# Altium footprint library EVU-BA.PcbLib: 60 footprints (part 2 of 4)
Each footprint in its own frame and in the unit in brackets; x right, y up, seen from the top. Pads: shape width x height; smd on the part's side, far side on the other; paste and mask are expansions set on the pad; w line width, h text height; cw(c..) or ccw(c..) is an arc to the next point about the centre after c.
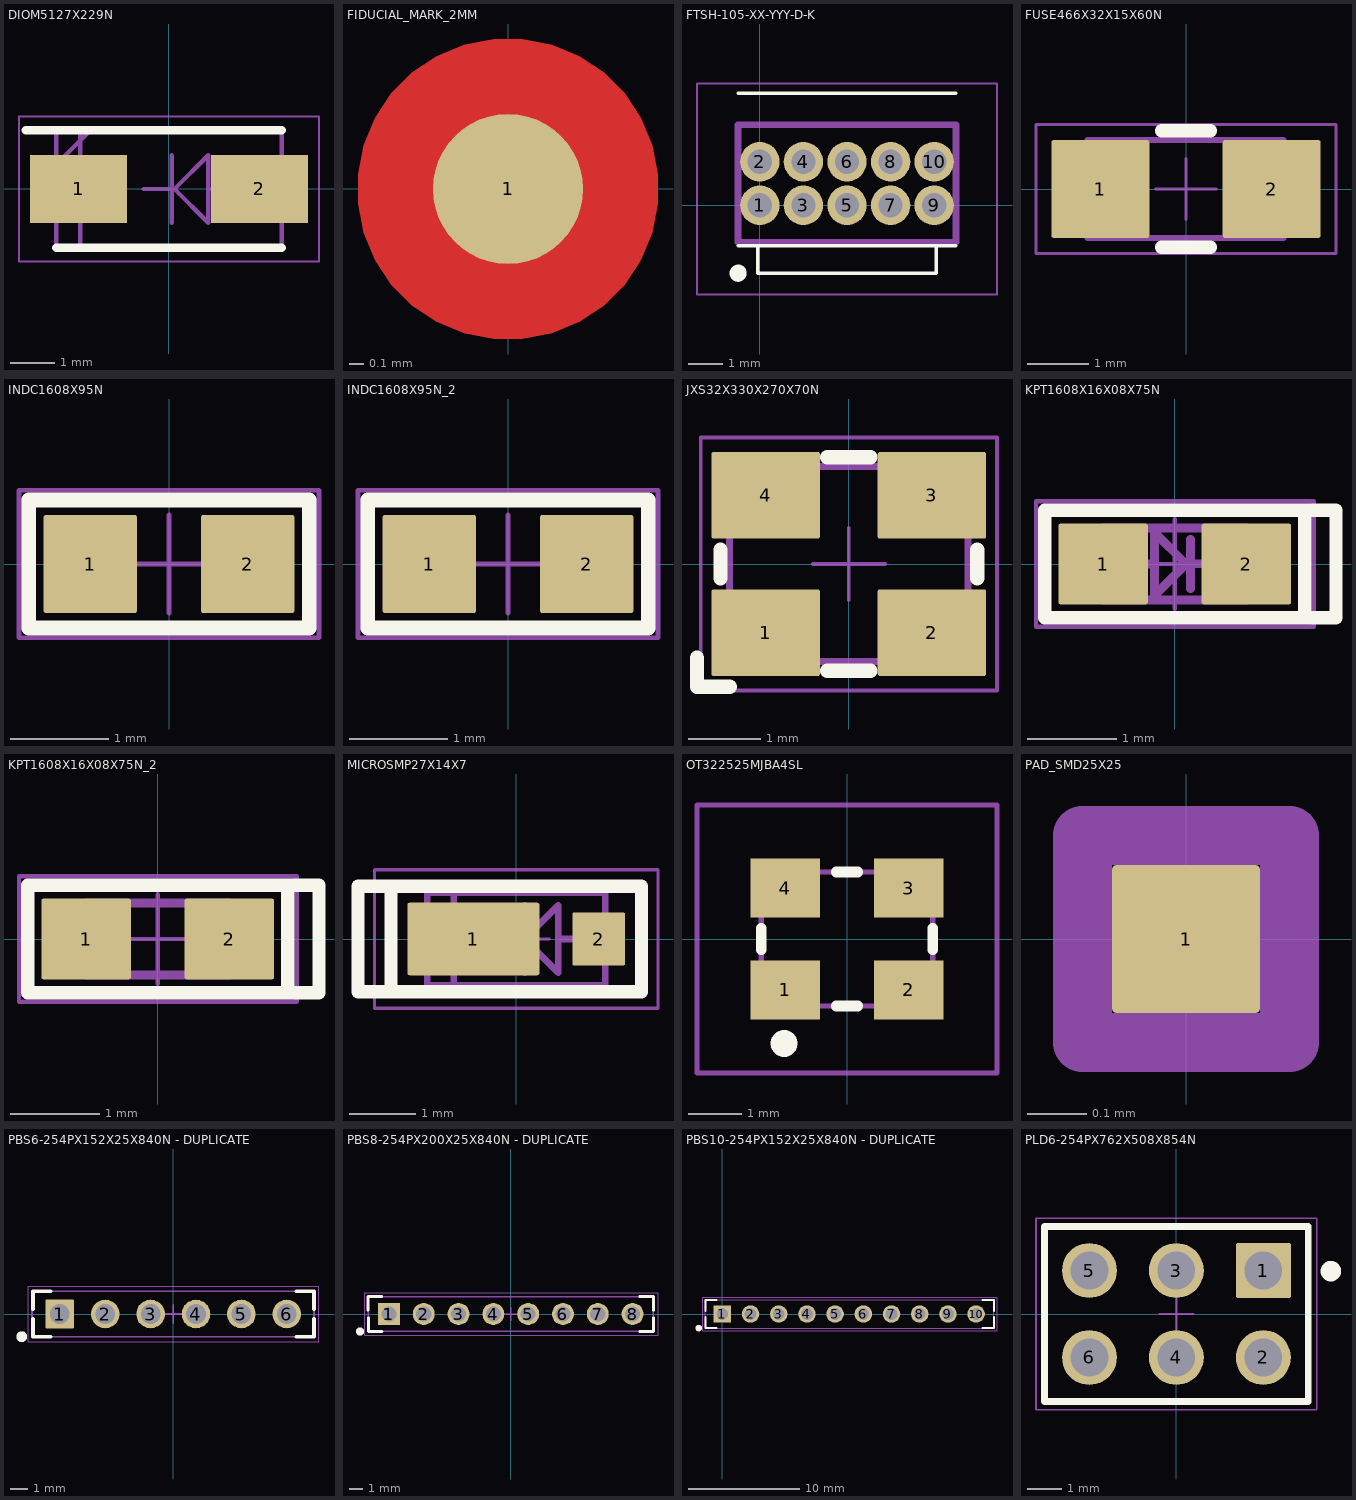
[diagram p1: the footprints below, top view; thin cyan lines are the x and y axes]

## DIOM5127X229N [mm]
pads (2):
  rect 2.2x1.55 smd: 1(-2.05,0) 2(2.05,0)
Top Overlay:
  lines w0.2: -3.24,1.332 -2.825,1.332 2.552,1.332 ; -2.552,-1.332 2.552,-1.332
Top Assembly:
  lines w0.1: -2.014,-1.332 -2.014,1.332 ; -0.572,0 0.064,0 ; 0.064,-0.762 0.064,0.762 ; 0.889,0 1.524,0 ; -2.552,-1.332 2.552,-1.332 2.552,1.332 -2.552,1.332 -2.552,-1.332 ; 0.127,0 0.889,-0.762 0.889,0.762 0.127,0
Mechanical 13:
  lines w0.1: -2.552,0.558 -1.778,1.332 ; -2.552,-1.332 2.552,-1.332 2.552,1.332 -2.552,1.332 -2.552,-1.332
Top Courtyard:
  lines w0.05: -3.4,-1.645 3.4,-1.645 3.4,1.645 -3.4,1.645 -3.4,-1.645
3D body "ES1B-E3_61T.stp": height 2.29, standoff 0, extent -2.552,-1.332 2.552,1.332

## FIDUCIAL_MARK_2MM [mil]
pads (1):
  round 40 smd paste+8.28 mask+20: 1(0,0)
Top Layer:
  pour cut-out: 0,-40 -3.94,-40 -11.67,-38.46 -18.95,-35.45 -25.5,-31.07 -31.07,-25.5 -35.45,-18.95 -38.46,-11.67 -40,-3.94 -40,0 -40,3.94 -38.46,11.67 -35.45,18.95 -31.07,25.5 -25.5,31.07 -18.95,35.45 -11.67,38.46 -3.94,40 0,40 3.94,40 11.67,38.46 18.95,35.45 25.5,31.07 31.07,25.5 35.45,18.95 38.46,11.67 40,3.94 40,0 40,-3.94 38.46,-11.67 35.45,-18.95 31.07,-25.5 25.5,-31.07 18.95,-35.45 11.67,-38.46 3.94,-40

## FTSH-105-XX-YYY-D-K [mm]
pads (10):
  round 1.15 hole 0.71: 1(0,0) 2(0,1.27) 3(1.27,0) 4(1.27,1.27) 5(2.54,0) 6(2.54,1.27) 7(3.81,0) 8(3.81,1.27) 9(5.08,0) 10(5.08,1.27)
Top Overlay:
  circle w0.25: c-0.635,-1.981 r0.125
  lines w0.1: -0.635,-1.182 5.715,-1.182 ; -0.635,3.264 5.715,3.264 ; -0.06,-1.981 -0.06,-1.182 5.14,-1.182 5.14,-1.981 -0.06,-1.981
Top Assembly:
  circle w0.25: c0,0 r0.125
  lines w0.1: -0.635,-1.08 5.715,-1.08 5.715,2.35 -0.635,2.35 -0.635,-1.08
Mechanical 13:
  lines w0.2: -0.635,-1.08 5.715,-1.08 5.715,2.35 -0.635,2.35 -0.635,-1.08
Top Courtyard:
  lines w0.05: -1.835,-2.6 6.915,-2.6 6.915,3.55 -1.835,3.55 -1.835,-2.6
3D body "FTSH-105-01-F-D-K.stp": height 5.71, standoff -2.29, extent -0.635,-1.905 5.715,3.175

## FUSE466X32X15X60N [mm]
pads (2):
  rrect5% 1.6x1.6 smd mask+0.05: 1(-1.4,0) 2(1.4,0)
Top Overlay:
  lines w0.22: -0.4,-0.95 0.4,-0.95 ; -0.4,0.95 0.4,0.95
Top Assembly:
  lines w0.1: -1.205,-0.799 -1.205,0.801 ; 1.195,-0.799 1.195,0.801 ; -1.605,-0.799 -1.605,0.801 1.595,0.801 1.595,-0.799 -1.605,-0.799
Top Designator:
  text ".Designator" at -3.25,-0.3 h1.5
Mechanical 9:
  text ".MARK" at -1.575,-0.35 h1.5
Top Courtyard:
  lines w0.05: -0.5,0 0.5,0 ; 0,-0.5 0,0.5 ; -2.45,-1.05 -2.45,1.05 2.45,1.05 2.45,-1.05 -2.45,-1.05
3D body "FUSE466.STEP": height 0.66, standoff 0, extent -1.65,-0.8 1.65,0.8

## INDC1608X95N [mm]
pads (2):
  rrect5% 0.95x1 smd mask+0.07: 1(-0.8,0) 2(0.8,0)
Top Overlay:
  lines w0.15: -1.425,-0.65 -1.425,0.65 1.425,0.65 1.425,-0.65 -1.425,-0.65
Top Assembly:
  lines w0.1: -1.45,-0.65 -1.45,0.65 1.45,0.65 1.45,-0.65 -1.45,-0.65
Top Designator:
  text ".Designator" at -3.25,-0.3 h1.5
Top Courtyard:
  lines w0.05: -0.5,0 0.5,0 ; 0,-0.5 0,0.5 ; -1.525,-0.75 -1.525,0.75 1.525,0.75 1.525,-0.75 -1.525,-0.75
3D body "BLM18__TN1.STEP": height 0.65, standoff 0, extent -0.875,-0.475 0.875,0.475

## INDC1608X95N_2 [mm]
pads (2):
  rrect5% 0.95x1 smd mask+0.07: 1(-0.8,0) 2(0.8,0)
Top Overlay:
  lines w0.15: -1.425,-0.65 1.425,-0.65 1.425,0.65 -1.425,0.65 -1.425,-0.65
Top Assembly:
  lines w0.1: -1.45,-0.65 1.45,-0.65 1.45,0.65 -1.45,0.65 -1.45,-0.65
Top Designator:
  text ".Designator" at -3.25,-0.3 h1.5
Top Courtyard:
  lines w0.05: -0.5,0 0.5,0 ; 0,-0.5 0,0.5 ; -1.525,-0.75 1.525,-0.75 1.525,0.75 -1.525,0.75 -1.525,-0.75
3D body "BLM18__TN1.STEP": height 0.65, standoff 0, extent -0.875,-0.475 0.875,0.475

## JXS32X330X270X70N [mm]
pads (4):
  rrect5% 1.5x1.2 smd mask+0.07: 1(-1.15,-0.95) 2(1.15,-0.95) 3(1.15,0.95) 4(-1.15,0.95)
Top Overlay:
  lines w0.2: -2.1,-1.3 -2.1,-1.7 -1.65,-1.7 ; -1.775,-0.2 -1.775,0.2 ; -0.3,-1.475 0.3,-1.475 ; -0.3,1.475 0.3,1.475 ; 1.775,-0.2 1.775,0.2
Top Assembly:
  circle w0.254: c-1.092,-0.889 r0.15
  lines w0.1: -1.65,-0.408 -1.65,-0.386 ; -1.65,-1.35 1.65,-1.35 1.65,1.35 -1.65,1.35 -1.65,-1.35
Top Designator:
  text ".Designator" at -3.25,-0.3 h1.5
Mechanical 9:
  text ".MARK" at -1.65,-0.39 h1.5
Top Courtyard:
  lines w0.05: -0.5,0 0.5,0 ; 0,-0.5 0,0.5 ; -2.05,-1.75 2.05,-1.75 2.05,1.75 -2.05,1.75 -2.05,-1.75
3D body: height 0.76, standoff 0.75, extent -1.422,-1.149 -0.725,-0.451
3D body "JXS32.STEP": height 0.75, standoff 0, extent -1.65,-1.35 1.65,1.35

## KPT1608X16X08X75N [mm]
pads (2):
  rrect5% 1x0.9 smd mask+0.07: 1(-0.8,0) 2(0.8,0)
Top Overlay:
  lines w0.15: 1.45,-0.6 1.8,-0.6 1.8,0.6 1.45,0.6 ; 1.45,-0.6 1.45,0.6 ; 1.45,-0.6 -1.45,-0.6 -1.45,0.6 1.45,0.6 ; 1.45,-0.6 1.45,0.6
Top Assembly:
  lines w0.1: -0.45,0 -0.225,0 ; -0.225,-0.021 -0.225,0.35 ; 0.125,0 -0.225,0.35 ; 0.175,-0.275 0.175,0.275 ; 0.35,0.003 0.128,0.003 -0.225,-0.35 -0.225,0.35 ; 0.55,-0.4 0.55,0.4 ; -0.8,-0.4 -0.8,0.4 0.8,0.4 0.8,-0.4 -0.8,-0.4
Top Designator:
  text ".Designator" at -3.275,-0.3 h1.5
Mechanical 9:
  text ".MARK" at -1.778,-0.354 h1.5
Top Courtyard:
  lines w0.05: -0.5,0 0.5,0 ; 0,-0.5 0,0.5 ; -1.55,-0.7 -1.55,0.7 1.55,0.7 1.55,-0.7 -1.55,-0.7
3D body: height 0.76, standoff 0.75, extent 0,-0.225 0.425,0.225
3D body "KPT-1608.STEP": height 0.75, standoff 0, extent -0.8,-0.4 0.8,0.4

## KPT1608X16X08X75N_2 [mm]
pads (2):
  rrect5% 1x0.9 smd mask+0.07: 1(-0.8,0) 2(0.8,0)
Top Overlay:
  lines w0.15: 1.45,-0.6 1.8,-0.6 1.8,0.6 1.45,0.6 ; 1.45,-0.6 1.45,0.6 ; 1.45,-0.6 -1.45,-0.6 -1.45,0.6 1.45,0.6 ; 1.45,-0.6 1.45,0.6
Top Assembly:
  lines w0.1: 0.55,-0.4 0.55,0.4 ; -0.8,-0.4 -0.8,0.4 0.8,0.4 0.8,-0.4 -0.8,-0.4
Top Designator:
  text ".Designator" at -3.275,-0.3 h1.5
Mechanical 9:
  text ".MARK" at -1.778,-0.354 h1.5
Top Courtyard:
  lines w0.05: -0.5,0 0.5,0 ; 0,-0.5 0,0.5 ; -1.55,-0.7 -1.55,0.7 1.55,0.7 1.55,-0.7 -1.55,-0.7
3D body: height 0.76, standoff 0.75, extent 0,-0.225 0.425,0.225
3D body "KPT-1608.STEP": height 0.75, standoff 0, extent -0.8,-0.4 0.8,0.4

## MICROSMP27X14X7 [mm]
pads (2):
  rrect5% 2x1.1 smd mask+0.07: 1(-0.65,0)
  rrect5% 0.8x0.8 smd mask+0.07: 2(1.25,0)
Top Overlay:
  lines w0.2: -1.9,-0.8 -2.4,-0.8 -2.4,0.8 -1.9,0.8 ; -1.9,-0.8 -1.9,0.8 ; -1.9,-0.8 -1.9,0.8 ; -1.9,-0.8 1.9,-0.8 1.9,0.8 -1.9,0.8
Top Assembly:
  lines w0.1: -0.95,-0.7 -0.95,0.7 ; -0.381,0 0.127,0 ; 0.127,-0.508 0.127,0.508 ; 0.635,0 1.143,0 ; 0.127,0 0.635,0.508 0.635,-0.508 0.127,0 ; -1.35,-0.7 1.35,-0.7 1.35,0.7 -1.35,0.7 -1.35,-0.7
Top Designator:
  text ".Designator" at -3.275,-0.3 h1.5
Mechanical 9:
  text ".MARK" at -1.778,-0.354 h1.5
Top Courtyard:
  lines w0.05: -0.5,0 0.5,0 ; 0,-0.5 0,0.5 ; -2.15,-1.05 -2.15,1.05 2.15,1.05 2.15,-1.05 -2.15,-1.05
3D body: height 0.74, standoff 0.73, extent -1.013,-0.625 -0.825,0.625
3D body "MicroSMP.STEP": height 0.7, standoff 0, extent -1.35,-0.7 1.35,0.7

## OT322525MJBA4SL [mm]
pads (4):
  rect 1.3x1.1 smd: 1(-1.15,-0.95) 2(1.15,-0.95) 3(1.15,0.95) 4(-1.15,0.95)
Top Overlay:
  lines w0.2: -1.6,-0.2 -1.6,0.2 ; -0.2,-1.25 0.2,-1.25 ; -0.2,1.25 0.2,1.25 ; 1.6,-0.2 1.6,0.2
  lines w0.25: -1.175,-2.075 ccw(c-1.175,-1.95) -1.175,-1.825 ccw(c-1.175,-1.95) -1.175,-2.075
Top Assembly:
  lines w0.1: -1.6,-1.25 1.6,-1.25 1.6,1.25 -1.6,1.25 -1.6,-1.25
  lines w0.25: -1.025,-0.9 ccw(c-1.025,-0.775) -1.025,-0.65 ccw(c-1.025,-0.775) -1.025,-0.9
Mechanical 13:
  lines w0.1: -1.6,-1.25 1.6,-1.25 1.6,1.25 -1.6,1.25 -1.6,-1.25
Top Courtyard:
  lines w0.1: -2.8,-2.5 2.8,-2.5 2.8,2.5 -2.8,2.5 -2.8,-2.5
3D body "OT322525MJBA4SL.stp": height 1.1, standoff 0, extent -1.69,-1.39 1.69,1.39

## PAD_SMD25X25 [mm]
pads (1):
  rrect5% 0.25x0.25 smd mask+0.07: 1(0,0)
Top Assembly:
  lines w0.1: -0.175,-0.175 -0.175,0.175 0.175,0.175 0.175,-0.175 -0.175,-0.175
Top Designator:
  text ".Designator" at -3.275,-0.3 h1.5

## PBS6-254PX152X25X840N - DUPLICATE [mil]
height 330.71
pads (6):
  rrect5% 63x63 hole 43.31 mask+2.76: 1(-250,0)
  round 63 hole 43.31 mask+2.76: 2(-150,0) 3(-50,0) 4(50,0) 5(150,0) 6(250,0)
Top Overlay:
  circle w11.81: c-334,-50 r5.91
  lines w7.87: -309,-10.63 -309,-50 -269.63,-50 ; -309,10.63 -309,50 -269.63,50 ; 270.63,-50 310,-50 310,-10.63 ; 270.63,50 310,50 310,10.63
Bottom Overlay:
  circle w11.81: c-311,50 r5.91
Top Assembly:
  circle w11.81: c-249.02,0.98 r5.91
  lines w3.94: -311,-50 310,-50 310,50 -311,50 -311,-50
Top Designator:
  text ".Designator" at 127.95,11.81 h59.06
Top Courtyard:
  lines w1.97: -319,-61.02 321,-61.02 321,61.02 -319,61.02 -319,-61.02
  lines w3.94: -19.68,0 19.68,0 ; 0,-19.68 0,19.68
3D body "PBS-6.step": height 334.65, standoff -118.11, extent -309.84,-50 309.84,48.43

## PBS8-254PX200X25X840N - DUPLICATE [mil]
height 330.71
pads (8):
  rrect5% 63x63 hole 43.31 mask+2.76: 1(-350,0)
  round 63 hole 43.31 mask+2.76: 2(-250,0) 3(-150,0) 4(-50,0) 5(50,0) 6(150,0) 7(250,0) 8(350,0)
Top Overlay:
  circle w11.81: c-433,-50 r5.91
  lines w7.87: -410,10.63 -410,50 -370.63,50 ; -409,-10.63 -409,-50 -369.63,-50 ; 370.63,-50 410,-50 410,-10.63 ; 370.63,50 410,50 410,10.63
Bottom Overlay:
  circle w11.81: c-409,50 r5.91
Top Assembly:
  circle w11.81: c-350.39,0 r5.91
  lines w3.94: -409,-50 410,-50 410,50 -409,50 -409,-50
Top Designator:
  text ".Designator" at 127.95,11.81 h59.06
Top Courtyard:
  lines w1.97: -419,-61.02 -419,61.02 423,61.02 423,-61.02 -419,-61.02
  lines w3.94: -19.68,0 19.68,0 ; 0,-19.68 0,19.68
3D body "PBS-8.step": height 334.65, standoff -118.11, extent -409.84,-49.21 409.84,49.21

## PBS10-254PX152X25X840N - DUPLICATE [mm]
height 1.27
pads (10):
  rect 1.575x1.575 hole 1.05: 1(0,0)
  round 1.575 hole 1.05: 2(2.54,0) 3(5.08,0) 4(7.62,0) 5(10.16,0) 6(12.7,0) 7(15.24,0) 8(17.78,0) 9(20.32,0) 10(22.86,0)
Top Overlay:
  circle w0.3: c-2.134,-1.27 r0.15
  lines w0.2: -1.52,-0.27 -1.52,-1.27 -0.52,-1.27 ; -1.52,0.27 -1.52,1.27 -0.52,1.27 ; 23.46,-1.27 24.46,-1.27 24.46,-0.27 ; 23.46,1.27 24.46,1.27 24.46,0.27
Bottom Overlay:
  circle w0.3: c-1.52,1.27 r0.15
Top Assembly:
  circle w0.3: c0,0 r0.15
  lines w0.1: -1.52,-1.27 -1.52,1.27 24.46,1.27 24.46,-1.27 -1.473,-1.27
Mechanical 12:
  lines w0.1: -1.52,-1.27 -1.52,1.27 24.46,1.27 24.46,-1.27 -1.52,-1.27
Top Courtyard:
  lines w0.05: -1.77,-1.52 -1.77,1.52 24.74,1.52 24.74,-1.52 -1.77,-1.52
3D body "PBS-10.step": height 8.5, standoff -3, extent -1.52,-1.25 24.38,1.25

## PLD6-254PX762X508X854N [mil]
pads (6):
  rrect5% 63x63 hole 43.31 mask+2.76: 1(100,50)
  round 63 hole 43.31 mask+2.76: 2(100,-50) 3(0,50) 4(0,-50) 5(-100,50) 6(-100,-50)
Top Overlay:
  circle w11.81: c177.56,49.21 r5.91
  lines w7.87: -151.57,-100.39 -151.57,100.39 151.57,100.39 151.57,-100.39 -151.57,-100.39
Top Assembly:
  circle w11.81: c100,49.21 r5.91
  lines w3.94: -151.57,-100.39 -151.57,100.39 151.57,100.39 151.57,-100.39 -151.57,-100.39
Top Designator:
  text ".Designator" at -127.95,-11.81 h59.06
Top Courtyard:
  lines w1.97: -19.68,0 19.68,0 ; 0,-19.68 0,19.68 ; -161.42,-110.24 -161.42,110.24 161.42,110.24 161.42,-110.24 -161.42,-110.24
3D body "PCB_Jumper.STEP": height 639.37, standoff 98.82, extent 54.13,-208.66 146.65,-11.81
3D body "BPDC-06.stp": height 337.35, standoff -116.98, extent -150,-101.18 150,98.82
